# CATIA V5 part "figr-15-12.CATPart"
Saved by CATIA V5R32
Part number: Part1
Bounding box of the stored display mesh (mm): x -50 to 50, y -32.5 to 33.5, z -52 to 1
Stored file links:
  D:\PROJECTS\Project 2022\CATIA V5 6R 2022\Resources\Part Files\c15_catia_v5_6r2022_prt\figr-15-12.CATPart
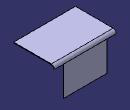
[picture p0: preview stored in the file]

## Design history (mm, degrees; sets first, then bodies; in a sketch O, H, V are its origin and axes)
SheetMetalParameters1: Thickness 1, BendRadius 4, KFactor 0.475772 {= log(min(100,max(20*SheetMetalParameters1.BendRadius,SheetMetalParameters1.Thickness)/SheetMetalParameters1.Thickness))/log(100)/2}, ReliefRadialLength 4, ReliefAxialLength 4, MinimumBendRadius 0
Body1 (main body)
  Sketch1 on xy-plane, origin (0, 0, 0), H (1, 0, 0), V (0, 1, 0)
    line L1 (-50, 32.5) -> (50, 32.5)
    line L2 (50, 32.5) -> (50, -32.5)
    line L3 (50, -32.5) -> (-50, -32.5)
    line L4 (-50, -32.5) -> (-50, 32.5)
    length L1 = 100
    length L2 = 65
    horizontal: L1 H, L3 H
    vertical: L2 V, L4 V
    symmetry: L4 L2 V, L1 L3 H
  Wall1: Thickness 1, Profile Sketch1
  d_NewWallOnEdge1: NewWallOnEdge_Edge edge [face of Wall1 | face of Wall1], NewWallOnEdge_Length 53, NewWallOnEdge_HeightLimitOffset 0, NewWallOnEdge_WidthOffset1 -15, NewWallOnEdge_WidthOffset2 -15, NewWallOnEdge_Angle 90, NewWallOnEdge_BendRadiusValue 4 {= SheetMetalParameters1.BendRadius}, NewWallOnEdge_BendTable SheetMetalParameters1, KFacteur 0.475772 {= log(min(100,max(20*d_NewWallOnEdge1.Radius,SheetMetalParameters1.Thickness)/SheetMetalParameters1.Thickness))/log(100)/2}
